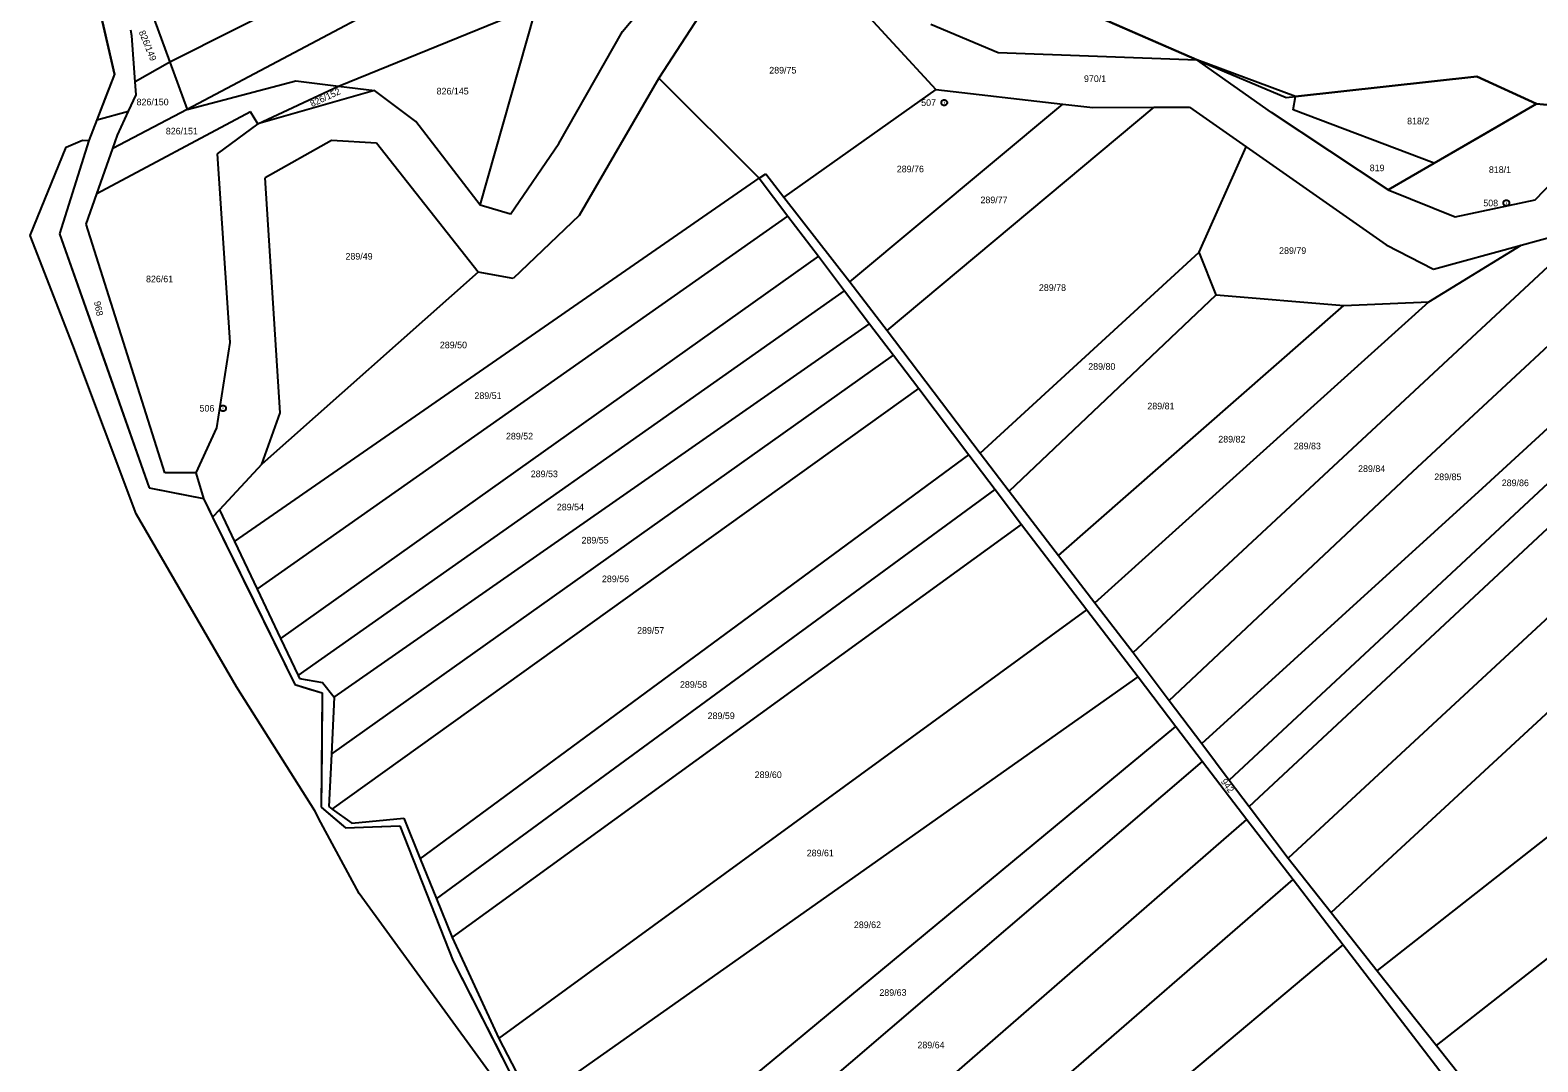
# Model space of a CAD drawing. Extents: x -593358 to -590116, y -1072518 to -1068420.
# Drawn here: x -592853.9 to -592467.4, y -1071189.7 to -1070925.3 of the extents above; entities that cross this region are included whole.
import ezdxf

# ---------------------------------------------------------------- set-up
doc = ezdxf.new("R2010")
doc.units = 0
for name, color, linetype in [('katastrální hranice', 7, 'Continuous'), ('lesy', 7, 'Continuous'), ('Obvod s Petrovicemi', 7, 'Continuous'), ('Parcela KN', 7, 'Continuous'), ('Parcela ZE', 7, 'Continuous'), ('Parcelní číslo', 7, 'Continuous'), ('vnější obvod_šetřený', 7, 'Continuous'), ('Vrstva 17', 7, 'Continuous'), ('Vrstva 24', 7, 'Continuous')]:
    doc.layers.add(name, color=color, linetype=linetype)

msp = doc.modelspace()

# ---------------------------------------------------------------- linework, layer by layer
at = {"layer": 'katastrální hranice'}
for p, q in [((-592832.3, -1070936.59), (-592837.43, -1070914.17)), ((-592832.3, -1070936.59), (-592836.81, -1070948.28)), ((-592836.81, -1070948.28), (-592838.86, -1070953.6)), ((-592838.86, -1070953.6), (-592846.36, -1070977.45)), ((-592846.36, -1070977.45), (-592823.42, -1071042.56)), ((-592823.42, -1071042.56), (-592809.46, -1071045.34)), ((-592809.46, -1071045.34), (-592807.14, -1071050.07)), ((-592807.14, -1071050.07), (-592786.07, -1071093)), ((-592786.07, -1071093), (-592779.04, -1071095.13)), ((-592779.04, -1071095.13), (-592779.31, -1071124.45)), ((-592779.31, -1071124.45), (-592773.07, -1071129.75)), ((-592773.07, -1071129.75), (-592759.17, -1071129.24)), ((-592759.17, -1071129.24), (-592745.47, -1071163.9)), ((-592745.47, -1071163.9), (-592723.98, -1071206.11))]:
    msp.add_line(p, q, dxfattribs=at)
at = {"layer": 'lesy'}
for points in [[(-592370.8, -1070941.28), (-592400.84, -1070929.68), (-592419.44, -1070939.96), (-592446.39, -1070946.25), (-592467.72, -1070944.19), (-592483.05, -1070937.18), (-592529.51, -1070942.3), (-592554.86, -1070932.86), (-592614.5, -1070906.86), (-592671.86, -1070870.49), (-592693.73, -1070840.44), (-592683.82, -1070829.7), (-592778.79, -1070686.39), (-592778.79, -1070686.39)], [(-592505.75, -1070966.18), (-592493.97, -1070959.37), (-592480.845, -1070951.78), (-592467.72, -1070944.19)]]:
    msp.add_lwpolyline(points, dxfattribs=at)
at = {"layer": 'Obvod s Petrovicemi'}
msp.add_lwpolyline([(-592522.15, -1071505.61), (-592558.14, -1071461.25), (-592584.29, -1071458.98), (-592598.025, -1071420.11), (-592611.76, -1071381.24), (-592623.21, -1071361.17), (-592662.33, -1071297.04), (-592671.15, -1071288.43), (-592694.94, -1071262.33), (-592709.62, -1071235.525), (-592724.3, -1071208.72), (-592769.58, -1071146.52), (-592779.36, -1071128.32), (-592780.91, -1071125.35), (-592801.03, -1071093.6), (-592826.77, -1071049.24), (-592843, -1071006.02), (-592853.91, -1070977.89), (-592844.7, -1070955.31), (-592840.46, -1070953.51), (-592838.86, -1070953.6)], dxfattribs=at)
at = {"layer": 'Parcela KN'}
for p, q in [((-592702.07, -1070925.64), (-592682.28, -1070901.89)), ((-592614.5, -1070906.86), (-592554.86, -1070932.86)), ((-592677.46, -1070914), (-592692.75, -1070937.56)), ((-592649.13, -1070910.72), (-592621.72, -1070940.48)), ((-592738.55, -1070970.14), (-592724.64, -1070921.14)), ((-592827.84, -1070926.78), (-592828.08, -1070925.25)), ((-592822.17, -1070922.3), (-592818.1, -1070933.46)), ((-592718.34, -1070954.34), (-592702.07, -1070925.64)), ((-592623.05, -1070923.78), (-592605.77, -1070931.03)), ((-592826.98, -1070938.56), (-592827.84, -1070926.78)), ((-592818.1, -1070933.46), (-592813.66, -1070945.62)), ((-592605.77, -1070931.03), (-592554.86, -1070932.86)), ((-592535.69, -1070946.38), (-592554.86, -1070932.86)), ((-592554.86, -1070932.86), (-592531.91, -1070942.56)), ((-592529.51, -1070942.3), (-592483.05, -1070937.18)), ((-592483.05, -1070937.18), (-592467.72, -1070944.19)), ((-592826.74, -1070941.86), (-592826.98, -1070938.56)), ((-592813.66, -1070945.62), (-592785.84, -1070938.31)), ((-592765.65, -1070940.73), (-592795.58, -1070949.27)), ((-592785.84, -1070938.31), (-592774.9, -1070939.62)), ((-592774.9, -1070939.62), (-592765.65, -1070940.73)), ((-592755.01, -1070948.68), (-592765.65, -1070940.73)), ((-592692.75, -1070937.56), (-592713.19, -1070972.78)), ((-592621.72, -1070940.48), (-592589.19, -1070944.25)), ((-592828.69, -1070946.07), (-592826.74, -1070941.86)), ((-592589.19, -1070944.25), (-592581.52, -1070945.14)), ((-592581.52, -1070945.14), (-592565.75, -1070945.05)), ((-592565.75, -1070945.05), (-592556.74, -1070945)), ((-592556.74, -1070945), (-592542.17, -1070955.21)), ((-592531.91, -1070942.56), (-592529.51, -1070942.3)), ((-592530.14, -1070945.69), (-592529.51, -1070942.3)), ((-592467.72, -1070944.19), (-592493.97, -1070959.37)), ((-592467.72, -1070944.19), (-592446.39, -1070946.25)), ((-592836.81, -1070948.28), (-592828.69, -1070946.07)), ((-592831.52, -1070952.16), (-592828.69, -1070946.07)), ((-592738.55, -1070970.14), (-592755.01, -1070948.68)), ((-592505.75, -1070966.18), (-592535.69, -1070946.38)), ((-592493.97, -1070959.37), (-592530.14, -1070945.69)), ((-592468.06, -1070968.74), (-592446.39, -1070946.25)), ((-592832.72, -1070955.59), (-592831.52, -1070952.16)), ((-592795.58, -1070949.27), (-592805.98, -1070956.98)), ((-592836.81, -1070967.26), (-592832.72, -1070955.59)), ((-592776.64, -1070953.6), (-592793.69, -1070963.14)), ((-592765.09, -1070954.27), (-592776.64, -1070953.6)), ((-592739.06, -1070987.29), (-592765.09, -1070954.27)), ((-592730.8, -1070972.45), (-592718.34, -1070954.34)), ((-592542.17, -1070955.21), (-592506.28, -1070980.35)), ((-592805.98, -1070956.98), (-592802.76, -1071005.37)), ((-592493.97, -1070959.37), (-592505.75, -1070966.18)), ((-592789.78, -1071023.34), (-592793.69, -1070963.14)), ((-592839.51, -1070974.97), (-592836.81, -1070967.26)), ((-592505.75, -1070966.18), (-592488.64, -1070973.15)), ((-592730.8, -1070972.45), (-592738.55, -1070970.14)), ((-592488.64, -1070973.15), (-592468.06, -1070968.74)), ((-592819.37, -1071038.71), (-592839.51, -1070974.97)), ((-592713.19, -1070972.78), (-592730.08, -1070988.92)), ((-592471.69, -1070980.4), (-592453.58, -1070975.43)), ((-592506.28, -1070980.35), (-592494.18, -1070986.58)), ((-592494.18, -1070986.58), (-592471.69, -1070980.4)), ((-592739.06, -1070987.29), (-592794.49, -1071036.51)), ((-592730.08, -1070988.92), (-592739.06, -1070987.29)), ((-592802.76, -1071005.37), (-592806.14, -1071027.22)), ((-592794.49, -1071036.51), (-592789.78, -1071023.34)), ((-592806.14, -1071027.22), (-592811.46, -1071038.77)), ((-592794.49, -1071036.51), (-592805.41, -1071048.22)), ((-592811.46, -1071038.77), (-592819.37, -1071038.71)), ((-592811.46, -1071038.77), (-592809.46, -1071045.34)), ((-592805.41, -1071048.22), (-592807.14, -1071050.07)), ((-592805.41, -1071048.22), (-592801.56, -1071056.31)), ((-592801.56, -1071056.31), (-592795.73, -1071068.55)), ((-592795.73, -1071068.55), (-592789.71, -1071081.19)), ((-592789.71, -1071081.19), (-592785.21, -1071090.65)), ((-592785.21, -1071090.65), (-592784.82, -1071091.47)), ((-592784.82, -1071091.47), (-592778.97, -1071092.5)), ((-592778.97, -1071092.5), (-592775.99, -1071096.23)), ((-592775.99, -1071096.23), (-592776.7, -1071110.88)), ((-592776.7, -1071110.88), (-592777.34, -1071124.28)), ((-592777.34, -1071124.28), (-592776.46, -1071124.92)), ((-592776.46, -1071124.92), (-592771.48, -1071128.51)), ((-592771.48, -1071128.51), (-592758.14, -1071127.26)), ((-592758.14, -1071127.26), (-592753.9, -1071137.66)), ((-592753.9, -1071137.66), (-592749.73, -1071147.91)), ((-592749.73, -1071147.91), (-592745.69, -1071157.83)), ((-592745.69, -1071157.83), (-592733.75, -1071183.73)), ((-592733.75, -1071183.73), (-592725.07, -1071200.47))]:
    msp.add_line(p, q, dxfattribs=at)
at = {"layer": 'Parcela ZE'}
for p, q in [((-592702.55, -1070875.37), (-592818.1, -1070933.46)), ((-592693.32, -1070881.86), (-592813.66, -1070945.62)), ((-592774.9, -1070939.62), (-592718.96, -1070916.83)), ((-592818.1, -1070933.46), (-592826.98, -1070938.56)), ((-592795.58, -1070949.27), (-592774.9, -1070939.62)), ((-592692.75, -1070937.56), (-592667, -1070963.23)), ((-592621.72, -1070940.48), (-592660.69, -1070968.05)), ((-592643.76, -1070989.77), (-592589.19, -1070944.25)), ((-592634.24, -1071002.28), (-592565.75, -1070945.05)), ((-592797.44, -1070946.24), (-592836.81, -1070967.26)), ((-592813.66, -1070945.62), (-592832.72, -1070955.59)), ((-592795.58, -1070949.27), (-592797.44, -1070946.24)), ((-592554.26, -1070982.15), (-592542.17, -1070955.21)), ((-592499.49, -1071038.4), (-592410.74, -1070955.9)), ((-592481.64, -1071042.64), (-592388.56, -1070957.38)), ((-592801.56, -1071056.31), (-592667, -1070963.23)), ((-592667, -1070963.23), (-592665.34, -1070962.08)), ((-592667, -1070963.23), (-592659.64, -1070972.94)), ((-592665.34, -1070962.08), (-592660.69, -1070968.05)), ((-592660.69, -1070968.05), (-592643.76, -1070989.77)), ((-592795.73, -1071068.55), (-592659.64, -1070972.94)), ((-592659.64, -1070972.94), (-592651.82, -1070983.25)), ((-592571.15, -1071084.82), (-592453.58, -1070975.43)), ((-592651.82, -1070983.25), (-592789.71, -1071081.19)), ((-592651.82, -1070983.25), (-592645.15, -1070992.07)), ((-592610.35, -1071033.68), (-592554.26, -1070982.15)), ((-592549.87, -1070993.09), (-592554.26, -1070982.15)), ((-592495.36, -1070994.96), (-592471.69, -1070980.4)), ((-592643.76, -1070989.77), (-592634.24, -1071002.28)), ((-592785.21, -1071090.65), (-592645.15, -1070992.07)), ((-592645.15, -1070992.07), (-592638.7, -1071000.59)), ((-592602.92, -1071043.44), (-592549.87, -1070993.09)), ((-592580.98, -1071072.04), (-592495.36, -1070994.96)), ((-592549.87, -1070993.09), (-592517.18, -1070995.84)), ((-592517.18, -1070995.84), (-592495.36, -1070994.96)), ((-592590.26, -1071059.95), (-592517.18, -1070995.84)), ((-592775.99, -1071096.23), (-592638.7, -1071000.59)), ((-592638.7, -1071000.59), (-592632.62, -1071008.61)), ((-592634.24, -1071002.28), (-592610.35, -1071033.68)), ((-592776.7, -1071110.88), (-592632.62, -1071008.61)), ((-592632.62, -1071008.61), (-592626.13, -1071017.17)), ((-592776.46, -1071124.92), (-592626.13, -1071017.17)), ((-592626.13, -1071017.17), (-592613.31, -1071034.1)), ((-592610.35, -1071033.68), (-592602.92, -1071043.44)), ((-592541.45, -1071124.23), (-592442.87, -1071032.46)), ((-592753.9, -1071137.66), (-592613.31, -1071034.1)), ((-592613.31, -1071034.1), (-592606.55, -1071043.02)), ((-592458.28, -1071035.32), (-592546.53, -1071117.48)), ((-592561.92, -1071097.06), (-592499.49, -1071038.4)), ((-592749.73, -1071147.91), (-592606.55, -1071043.02)), ((-592606.55, -1071043.02), (-592599.78, -1071051.96)), ((-592602.92, -1071043.44), (-592590.26, -1071059.95)), ((-592553.56, -1071108.15), (-592481.64, -1071042.64)), ((-592745.69, -1071157.83), (-592599.78, -1071051.96)), ((-592599.78, -1071051.96), (-592583.04, -1071073.87)), ((-592590.26, -1071059.95), (-592580.98, -1071072.04)), ((-592447.86, -1071060.11), (-592531.45, -1071137.49)), ((-592520.43, -1071151.39), (-592427.69, -1071065.78)), ((-592580.98, -1071072.04), (-592571.15, -1071084.82)), ((-592733.75, -1071183.73), (-592583.04, -1071073.87)), ((-592583.04, -1071073.87), (-592569.91, -1071091.05)), ((-592571.15, -1071084.82), (-592561.92, -1071097.06)), ((-592725.07, -1071200.47), (-592569.91, -1071091.05)), ((-592569.91, -1071091.05), (-592560.19, -1071103.78)), ((-592561.92, -1071097.06), (-592553.56, -1071108.15)), ((-592702.85, -1071221.76), (-592560.19, -1071103.78)), ((-592560.19, -1071103.78), (-592553.36, -1071112.72)), ((-592508.57, -1071166.34), (-592432.46, -1071106.58)), ((-592553.56, -1071108.15), (-592546.53, -1071117.48)), ((-592686.37, -1071226.46), (-592553.36, -1071112.72)), ((-592553.36, -1071112.72), (-592541.97, -1071127.57)), ((-592546.53, -1071117.48), (-592541.45, -1071124.23)), ((-592541.45, -1071124.23), (-592531.45, -1071137.49)), ((-592493.38, -1071185.5), (-592416.89, -1071125.42)), ((-592684.28, -1071251.3), (-592541.97, -1071127.57)), ((-592541.97, -1071127.57), (-592530.16, -1071142.97)), ((-592531.45, -1071137.49), (-592520.43, -1071151.39)), ((-592674.67, -1071268.27), (-592530.16, -1071142.97)), ((-592530.16, -1071142.97), (-592517.34, -1071159.69)), ((-592520.43, -1071151.39), (-592508.57, -1071166.34)), ((-592567.61, -1071201.88), (-592517.34, -1071159.69)), ((-592517.34, -1071159.69), (-592491.69, -1071193.14)), ((-592508.57, -1071166.34), (-592493.38, -1071185.5)), ((-592493.38, -1071185.5), (-592479.28, -1071203.27))]:
    msp.add_line(p, q, dxfattribs=at)
at = {"layer": 'vnější obvod_šetřený'}
for p, q in [((-592837.43, -1070914.17), (-592834.865, -1070925.38)), ((-592834.865, -1070925.38), (-592832.3, -1070936.59)), ((-592832.3, -1070936.59), (-592834.555, -1070942.435)), ((-592834.555, -1070942.435), (-592836.81, -1070948.28)), ((-592836.81, -1070948.28), (-592837.835, -1070950.94)), ((-592837.835, -1070950.94), (-592838.86, -1070953.6)), ((-592838.86, -1070953.6), (-592842.61, -1070965.525)), ((-592842.61, -1070965.525), (-592846.36, -1070977.45)), ((-592846.36, -1070977.45), (-592834.89, -1071010.005)), ((-592834.89, -1071010.005), (-592823.42, -1071042.56)), ((-592823.42, -1071042.56), (-592816.44, -1071043.95)), ((-592816.44, -1071043.95), (-592809.46, -1071045.34)), ((-592809.46, -1071045.34), (-592808.3, -1071047.705)), ((-592808.3, -1071047.705), (-592807.14, -1071050.07)), ((-592807.14, -1071050.07), (-592796.605, -1071071.535)), ((-592796.605, -1071071.535), (-592786.07, -1071093)), ((-592786.07, -1071093), (-592782.555, -1071094.065)), ((-592782.555, -1071094.065), (-592779.04, -1071095.13)), ((-592779.04, -1071095.13), (-592779.175, -1071109.79)), ((-592779.175, -1071109.79), (-592779.31, -1071124.45)), ((-592779.31, -1071124.45), (-592776.19, -1071127.1)), ((-592776.19, -1071127.1), (-592773.07, -1071129.75)), ((-592773.07, -1071129.75), (-592766.12, -1071129.495)), ((-592766.12, -1071129.495), (-592759.17, -1071129.24)), ((-592759.17, -1071129.24), (-592752.32, -1071146.57))]:
    msp.add_line(p, q, dxfattribs=at)
msp.add_lwpolyline([(-592752.32, -1071146.57), (-592745.47, -1071163.9), (-592734.725, -1071185.005), (-592723.98, -1071206.11)], dxfattribs=at)
at = {"layer": 'Vrstva 24'}
for p, q in [((-592619.64, -1070943.86), (-592619.54, -1070943.86)), ((-592475.54, -1070969.6), (-592475.44, -1070969.6)), ((-592804.54, -1071022.19), (-592804.44, -1071022.19))]:
    msp.add_line(p, q, dxfattribs=at)
for points in [[(-592619.4, -1070943.14), (-592619.06, -1070943.33), (-592618.87, -1070943.67), (-592618.87, -1070944.06), (-592619.06, -1070944.4), (-592619.4, -1070944.59), (-592619.79, -1070944.59), (-592620.13, -1070944.4), (-592620.32, -1070944.06), (-592620.32, -1070943.67), (-592620.13, -1070943.33), (-592619.79, -1070943.14)], [(-592475.3, -1070968.88), (-592474.96, -1070969.07), (-592474.77, -1070969.41), (-592474.77, -1070969.8), (-592474.96, -1070970.14), (-592475.3, -1070970.33), (-592475.69, -1070970.33), (-592476.03, -1070970.14), (-592476.22, -1070969.8), (-592476.22, -1070969.41), (-592476.03, -1070969.07), (-592475.69, -1070968.88)], [(-592804.3, -1071021.47), (-592803.96, -1071021.66), (-592803.77, -1071022), (-592803.77, -1071022.39), (-592803.96, -1071022.73), (-592804.3, -1071022.92), (-592804.69, -1071022.92), (-592805.03, -1071022.73), (-592805.22, -1071022.39), (-592805.22, -1071022), (-592805.03, -1071021.66), (-592804.69, -1071021.47)]]:
    msp.add_lwpolyline(points, close=True, dxfattribs=at)

# ---------------------------------------------------------------- texts
at = {"layer": 'Parcelní číslo'}
for s, rotation, p in [('826/149', 292.15118, (-592826.101, -1070925.763)), ('826/152', 24.80907, (-592781.652, -1070945.036)), ('968', 281.43687, (-592837.571, -1070994.935)), ('942', 306.53242, (-592548.767, -1071117.901))]:
    msp.add_text(s, height=1.7, rotation=rotation, dxfattribs=at).set_placement(p)
for s, p in [('289/75', (-592664.44, -1070936.4)), ('970/1', (-592583.762, -1070938.59)), ('826/145', (-592749.711, -1070941.77)), ('826/150', (-592826.628, -1070944.55)), ('818/2', (-592500.922, -1070949.43)), ('826/151', (-592819.133, -1070952.01)), ('289/76', (-592631.743, -1070961.72)), ('819', (-592510.503, -1070961.44)), ('818/1', (-592479.961, -1070961.89)), ('289/77', (-592610.293, -1070969.64)), ('289/49', (-592773.073, -1070984.09)), ('289/79', (-592533.733, -1070982.63)), ('826/61', (-592824.205, -1070989.91)), ('289/78', (-592595.313, -1070992.12)), ('289/50', (-592748.876, -1071006.82)), ('289/80', (-592582.666, -1071012.33)), ('289/51', (-592740.012, -1071019.8)), ('289/81', (-592567.512, -1071022.48)), ('289/52', (-592731.933, -1071030.19)), ('289/82', (-592549.323, -1071030.97)), ('289/83', (-592529.987, -1071032.71)), ('289/84', (-592513.49, -1071038.52)), ('289/53', (-592725.577, -1071039.86)), ('289/85', (-592493.956, -1071040.62)), ('289/86', (-592476.66, -1071042.16)), ('289/54', (-592718.89, -1071048.36)), ('289/55', (-592712.567, -1071056.86)), ('289/56', (-592707.33, -1071066.77)), ('289/57', (-592698.32, -1071079.99)), ('289/58', (-592687.33, -1071093.84)), ('289/59', (-592680.24, -1071101.86)), ('289/60', (-592668.18, -1071116.97)), ('289/61', (-592654.835, -1071137.03)), ('289/62', (-592642.746, -1071155.43)), ('289/63', (-592636.21, -1071172.79)), ('289/64', (-592626.453, -1071186.24))]:
    msp.add_text(s, height=1.7, dxfattribs=at).set_placement(p)
at = {"layer": 'Vrstva 17'}
for s, p in [('507', (-592625.491, -1070944.71)), ('508', (-592481.391, -1070970.45)), ('506', (-592810.484, -1071023.04))]:
    msp.add_text(s, height=1.7, dxfattribs=at).set_placement(p)

doc.saveas('drawing.dxf')
